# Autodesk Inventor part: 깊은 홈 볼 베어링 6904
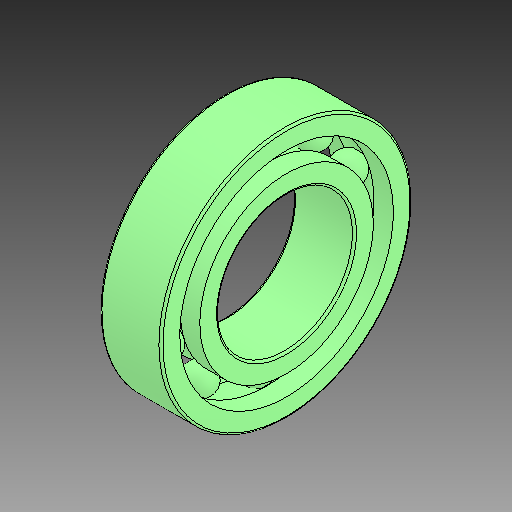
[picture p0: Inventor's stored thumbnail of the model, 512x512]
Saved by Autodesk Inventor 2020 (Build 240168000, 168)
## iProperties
Created: 2024-08
Part Number: 깊은 홈 볼 베어링 6904
Material: 강철, 연강
Description: 깊은 그루브 볼 베어링
Document SubType Name: Modeling
Designer: 1강의실14
Density: 7.85 g/cm^3
Appearance: 기본값
Author: jhkim
Sending System: Autodesk Inventor 2025
Preprocessor: ST-DEVELOPER v20
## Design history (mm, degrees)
feature "Solid1"
feature "Solid1:1"
feature "Solid1:2"
feature "Solid1:3"
feature "Solid1:4"
feature "Solid1:5"
feature "Solid1:6"
feature "Solid1:7"
feature "Solid1:8"
feature "Solid1:9"
feature "Solid1:10"
feature "Solid1:11"
node "솔리드1"
node "솔리드2"
node "솔리드3"
node "솔리드4"
node "솔리드5"
node "솔리드6"
node "솔리드7"
node "솔리드8"
node "솔리드9"
node "솔리드10"
node "솔리드11"
node "솔리드12"
